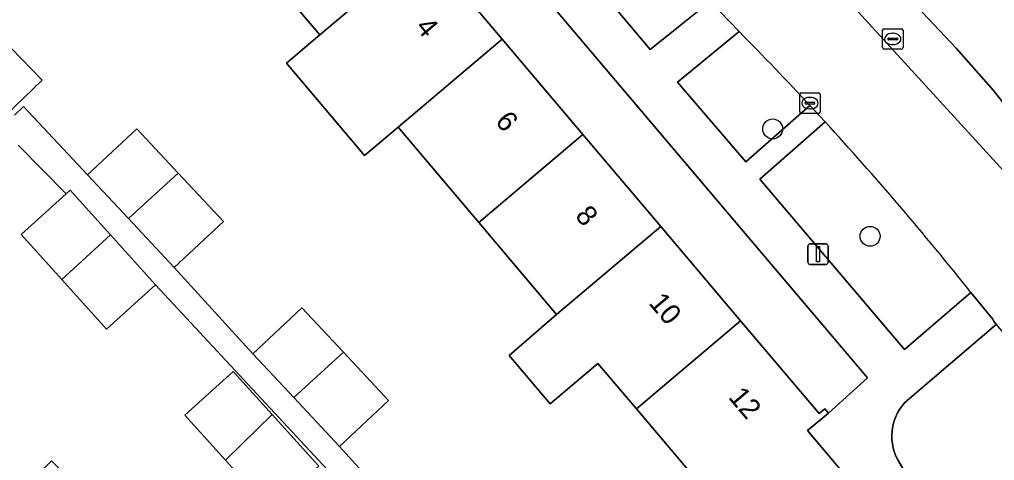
# Model space of a CAD drawing. Extents: x 157445 to 158888, y 383061 to 384688.
# Drawn here: x 158054.19 to 158101.94, y 383660.93 to 383682.54 of the extents above; entities that cross this region are included whole.
import ezdxf

# ---------------------------------------------------------------- set-up
doc = ezdxf.new("R2010")
doc.units = 0
for name, color, linetype in [('IMGEO_Boom', 7, 'Continuous'), ('IMGEO_Erf', 7, 'Continuous'), ('IMGEO_Groenvoorziening', 7, 'Continuous'), ('IMGEO_Kolk', 7, 'Continuous'), ('IMGEO_Lichtmast', 7, 'Continuous'), ('IMGEO_Pand', 7, 'Continuous'), ('IMGEO_Pand_nummerreeks', 7, 'Continuous'), ('IMGEO_Rijbaan_lokaal_open', 7, 'Continuous'), ('IMGEO_Voetpad_open', 7, 'Continuous')]:
    doc.layers.add(name, color=color, linetype=linetype)

msp = doc.modelspace()

# ---------------------------------------------------------------- linework, layer by layer
at = {"layer": 'IMGEO_Boom'}
for centre in [(158091.078, 383677.178), (158095.849, 383671.915)]:
    msp.add_circle(centre, 0.489, dxfattribs=at)
at = {"layer": 'IMGEO_Erf'}
for points in [[(158092.625, 383696.263), (158088.43, 383700.755), (158084.527, 383704.934), (158084.25, 383704.676), (158084.045, 383704.896), (158080.741, 383701.811), (158086.038, 383696.025), (158100.067, 383681.132), (158101.887, 383679.058), (158105.261, 383674.8), (158108.948, 383678.243), (158108.741, 383678.465), (158109.011, 383678.718), (158105.049, 383682.96), (158100.869, 383687.435), (158096.77, 383691.825)], [(158072.313, 383692.636), (158070.36, 383690.983), (158070.525, 383690.787), (158070.237, 383690.543), (158074, 383686.097), (158077.829, 383681.572), (158081.783, 383676.9), (158085.593, 383672.397), (158089.505, 383667.775), (158093.355, 383663.225), (158093.632, 383663.46), (158093.805, 383663.256), (158095.722, 383664.977)], [(158053.274, 383681.653), (158055.291, 383679.571), (158053.065, 383677.434), (158051.058, 383679.524), (158049.018, 383681.648), (158051.217, 383683.777)], [(158064.27, 383660.943), (158062.282, 383663.145), (158064.658, 383665.289), (158066.561, 383663.181), (158068.84, 383660.658), (158066.464, 383658.513)]]:
    msp.add_lwpolyline(points, close=True, dxfattribs=at)
for points in [[(158080.49, 383668.082), (158076.68, 383672.585), (158072.726, 383677.258), (158071.078, 383675.88), (158067.259, 383680.398), (158068.897, 383681.783), (158065.131, 383686.233)], [(158053.948, 383677.856), (158054.386, 383678.28), (158057.524, 383674.927), (158059.934, 383677.184), (158061.964, 383675.014), (158064.179, 383672.648), (158061.769, 383670.392), (158065.611, 383666.151), (158068.021, 383668.408), (158070.052, 383666.237), (158072.266, 383663.872), (158069.856, 383661.616), (158073.799, 383657.268)], [(158053.719, 383658.92), (158055.759, 383660.913), (158059.947, 383656.682), (158064.119, 383652.466), (158068.424, 383648.116), (158071.384, 383645.125), (158069.358, 383643.12), (158070.575, 383641.89), (158070.767, 383642.08), (158070.948, 383641.898), (158070.497, 383641.451), (158072.722, 383639.101), (158081.32, 383647.24), (158077.126, 383651.884), (158074.719, 383649.71), (158072.534, 383652.13), (158070.537, 383654.342), (158072.945, 383656.515), (158060.851, 383669.543), (158058.444, 383667.369), (158056.257, 383669.792), (158054.262, 383672.001), (158056.476, 383673.999), (158054.116, 383676.385)], [(158088.243, 383658.921), (158084.402, 383663.46), (158082.519, 383665.684), (158080.171, 383663.699), (158078.163, 383666.074), (158080.49, 383668.082)]]:
    msp.add_lwpolyline(points, dxfattribs=at)
at = {"layer": 'IMGEO_Groenvoorziening'}
msp.add_lwpolyline([(158081.806, 383690.454), (158079.964, 383692.414), (158078.718, 383693.741), (158078.291, 383694.107), (158077.833, 383694.433), (158077.347, 383694.717), (158076.838, 383694.957), (158076.31, 383695.15), (158075.767, 383695.295), (158075.212, 383695.391), (158074.806, 383695.43), (158074.307, 383695.428), (158073.811, 383695.381), (158073.321, 383695.29), (158073.153, 383695.248), (158085.078, 383681.064), (158088.008, 383683.429)], close=True, dxfattribs=at)
for points in [[(158089.434, 383681.946), (158086.414, 383679.474), (158089.769, 383675.56), (158092.902, 383678.334)], [(158093.643, 383677.531), (158090.443, 383674.723), (158097.528, 383666.368), (158100.789, 383669.164)], [(158102.019, 383667.598), (158097.557, 383663.779), (158097.416, 383663.61), (158097.291, 383663.43), (158097.182, 383663.238), (158097.091, 383663.038), (158097.018, 383662.831), (158096.964, 383662.618), (158096.929, 383662.401), (158096.914, 383662.181), (158096.918, 383661.961), (158096.942, 383661.743), (158096.985, 383661.527), (158097.048, 383661.316), (158097.129, 383661.112), (158097.203, 383660.961), (158101.786, 383653.06), (158105.141, 383646.908)]]:
    msp.add_lwpolyline(points, dxfattribs=at)
for centre, radius, start, end in [((157977.199, 383570.714), 158.017, 42.92697, 44.74268), ((157977.673, 383571.249), 157.305, 38.49534, 42.50392)]:
    msp.add_arc(centre, radius, start, end, dxfattribs=at)
at = {"layer": 'IMGEO_Kolk'}
for p, q in [((158096.46, 383681.163), (158096.46, 383682.015)), ((158096.535, 383682.089), (158097.387, 383682.089)), ((158096.948, 383681.869), (158096.973, 383681.869)), ((158097.461, 383682.015), (158097.461, 383681.163)), ((158096.719, 383681.583), (158096.719, 383681.595)), ((158097.157, 383681.546), (158096.759, 383681.546)), ((158096.762, 383681.632), (158097.16, 383681.632)), ((158096.971, 383681.309), (158096.946, 383681.309)), ((158097.203, 383681.595), (158097.203, 383681.583)), ((158097.387, 383681.089), (158096.535, 383681.089)), ((158092.401, 383678.016), (158092.401, 383678.868)), ((158092.476, 383678.942), (158093.328, 383678.942)), ((158093.402, 383678.868), (158093.402, 383678.016)), ((158092.66, 383678.436), (158092.66, 383678.448)), ((158093.098, 383678.399), (158092.7, 383678.399)), ((158092.703, 383678.485), (158093.101, 383678.485)), ((158092.889, 383678.722), (158092.914, 383678.722)), ((158093.144, 383678.448), (158093.144, 383678.436)), ((158093.328, 383677.942), (158092.476, 383677.942)), ((158092.912, 383678.162), (158092.887, 383678.162))]:
    msp.add_line(p, q, dxfattribs=at)
for points in [[(158096.46, 383681.163), (158096.46, 383682.015)], [(158096.535, 383682.089), (158097.387, 383682.089)], [(158097.461, 383682.015), (158097.461, 383681.163)], [(158097.387, 383681.089), (158096.535, 383681.089)], [(158092.401, 383678.016), (158092.401, 383678.868)], [(158092.476, 383678.942), (158093.328, 383678.942)], [(158093.402, 383678.868), (158093.402, 383678.016)], [(158093.328, 383677.942), (158092.476, 383677.942)]]:
    msp.add_lwpolyline(points, dxfattribs=at)
for centre, radius, start, end in [((158096.537, 383682.013), 0.0765, 91.552, 178.448), ((158096.537, 383682.013), 0.0765, 91.552, 178.448), ((158097.385, 383682.013), 0.0765, 1.552, 88.448), ((158097.385, 383682.013), 0.0765, 1.552, 88.448), ((158096.759, 383681.592), 0.0403, 85.8775, 175.7526), ((158096.756, 383681.582), 0.0366, 178.938, 274.7102), ((158097.16, 383681.589), 0.043, 264.8664, 352.4533), ((158097.164, 383681.594), 0.0386, 1.7309, 96.639), ((158096.537, 383681.165), 0.0765, 181.552, 268.448), ((158096.537, 383681.165), 0.0765, 181.552, 268.448), ((158097.385, 383681.165), 0.0765, 271.552, 358.448), ((158097.385, 383681.165), 0.0765, 271.552, 358.448), ((158092.478, 383678.866), 0.0765, 91.552, 178.448), ((158092.478, 383678.866), 0.0765, 91.552, 178.448), ((158093.326, 383678.866), 0.0765, 1.552, 88.448), ((158093.326, 383678.866), 0.0765, 1.552, 88.448), ((158092.7, 383678.445), 0.0403, 85.8775, 175.7526), ((158092.697, 383678.435), 0.0366, 178.938, 274.7102), ((158093.101, 383678.442), 0.043, 264.8664, 352.4533), ((158093.105, 383678.447), 0.0386, 1.7309, 96.639), ((158092.478, 383678.018), 0.0765, 181.552, 268.448), ((158092.478, 383678.018), 0.0765, 181.552, 268.448), ((158093.326, 383678.018), 0.0765, 271.552, 358.448), ((158093.326, 383678.018), 0.0765, 271.552, 358.448)]:
    msp.add_arc(centre, radius, start, end, dxfattribs=at)
for centre, major_axis, ratio, start_param, end_param in [((158096.947, 383681.589), (-0.387, 0.002), 0.722429, 4.712389, 7.853982), ((158096.972, 383681.589), (-0.39, 0.002), 0.717154, 1.570796, 4.712389), ((158092.888, 383678.442), (-0.387, 0.002), 0.722429, 4.712389, 7.853982), ((158092.913, 383678.442), (-0.39, 0.002), 0.717154, 1.570796, 4.712389)]:
    msp.add_ellipse(centre, major_axis=major_axis, ratio=ratio, start_param=start_param, end_param=end_param, dxfattribs=at)
at = {"layer": 'IMGEO_Lichtmast'}
for p, q in [((158092.803, 383670.641), (158092.803, 383671.441)), ((158092.803, 383671.441), (158092.803, 383670.641)), ((158092.903, 383671.541), (158093.693, 383671.541)), ((158093.693, 383671.541), (158092.903, 383671.541)), ((158093.793, 383671.441), (158093.793, 383670.641)), ((158093.793, 383670.641), (158093.793, 383671.441)), ((158093.693, 383670.541), (158092.903, 383670.541)), ((158092.903, 383670.541), (158093.693, 383670.541))]:
    msp.add_line(p, q, dxfattribs=at)
msp.add_lwpolyline([(158093.223, 383671.416), (158093.373, 383671.416), (158093.373, 383670.666), (158093.223, 383670.666), (158093.223, 383671.416)], dxfattribs=at)
for centre, start, end in [((158092.903, 383671.441), 90, 180), ((158092.903, 383671.441), 90, 180), ((158093.693, 383671.441), 0, 90), ((158093.693, 383671.441), 360, 90), ((158092.903, 383670.641), 180, 270), ((158092.903, 383670.641), 180, 270), ((158093.693, 383670.641), 270, 0), ((158093.693, 383670.641), 270, 0)]:
    msp.add_arc(centre, 0.1, start, end, dxfattribs=at)
at = {"layer": 'IMGEO_Pand'}
for points in [[(158074, 383686.097), (158070.237, 383690.543), (158070.525, 383690.787), (158070.36, 383690.983), (158066.544, 383687.753), (158064.686, 383686.181), (158064.846, 383685.992), (158065.131, 383686.233), (158068.897, 383681.783)], [(158072.726, 383677.258), (158077.829, 383681.572), (158074, 383686.097), (158068.897, 383681.783), (158067.259, 383680.398), (158071.078, 383675.88)], [(158053.274, 383681.653), (158051.058, 383679.524), (158053.065, 383677.434), (158055.291, 383679.571)], [(158076.68, 383672.585), (158081.783, 383676.9), (158077.829, 383681.572), (158072.726, 383677.258)], [(158061.964, 383675.014), (158059.934, 383677.184), (158057.524, 383674.927), (158059.528, 383672.786)], [(158085.593, 383672.397), (158081.783, 383676.9), (158076.68, 383672.585), (158080.49, 383668.082)], [(158061.964, 383675.014), (158059.528, 383672.786), (158061.769, 383670.392), (158064.179, 383672.648)], [(158056.67, 383674.174), (158056.476, 383673.999), (158054.262, 383672.001), (158056.257, 383669.792), (158058.65, 383671.981)], [(158085.593, 383672.397), (158080.49, 383668.082), (158078.163, 383666.074), (158080.171, 383663.699), (158082.519, 383665.684), (158084.402, 383663.46), (158089.505, 383667.775)], [(158058.65, 383671.981), (158056.257, 383669.792), (158058.444, 383667.369), (158060.851, 383669.543)], [(158067.616, 383664.009), (158070.052, 383666.237), (158068.021, 383668.408), (158065.611, 383666.151)], [(158089.505, 383667.775), (158084.402, 383663.46), (158088.243, 383658.921), (158087.941, 383658.665), (158088.124, 383658.449), (158088.385, 383658.67), (158090.381, 383656.311), (158090.136, 383656.104), (158090.324, 383655.883), (158094.937, 383659.925), (158095.138, 383660.101), (158094.951, 383660.322), (158094.707, 383660.115), (158092.782, 383662.391), (158093.805, 383663.256), (158093.632, 383663.46), (158093.355, 383663.225)], [(158067.616, 383664.009), (158069.856, 383661.616), (158072.266, 383663.872), (158070.052, 383666.237)], [(158064.27, 383660.943), (158066.561, 383663.181), (158064.658, 383665.289), (158062.282, 383663.145)], [(158064.27, 383660.943), (158066.464, 383658.513), (158068.84, 383660.658), (158066.561, 383663.181)]]:
    msp.add_lwpolyline(points, close=True, dxfattribs=at)
at = {"layer": 'IMGEO_Rijbaan_lokaal_open'}
for points in [[(158103.101, 383674.336), (158085.347, 383693.787), (158081.806, 383690.454), (158088.008, 383683.429), (158089.434, 383681.946)], [(158092.902, 383678.334), (158093.643, 383677.531)], [(158100.789, 383669.164), (158101.837, 383667.872), (158101.917, 383667.751), (158102.019, 383667.598), (158103.018, 383666.401)]]:
    msp.add_lwpolyline(points, dxfattribs=at)
for centre, radius, start, end in [((157977.199, 383570.714), 158.017, 42.92697, 44.74268), ((157977.673, 383571.249), 157.305, 38.49534, 42.50392)]:
    msp.add_arc(centre, radius, start, end, dxfattribs=at)
at = {"layer": 'IMGEO_Voetpad_open'}
for points in [[(158105.261, 383674.8), (158101.887, 383679.058), (158100.067, 383681.132), (158086.038, 383696.025), (158080.741, 383701.811), (158079.451, 383703.221), (158079.329, 383703.032), (158079.224, 383702.834), (158079.138, 383702.627), (158079.07, 383702.412), (158079.022, 383702.193), (158078.993, 383701.97), (158078.985, 383701.746), (158078.996, 383701.522), (158079.028, 383701.299), (158079.079, 383701.081), (158079.15, 383700.868), (158079.239, 383700.662), (158079.347, 383700.464), (158083.532, 383695.764), (158085.347, 383693.787), (158103.101, 383674.336)], [(158090.443, 383674.723), (158093.643, 383677.531), (158092.902, 383678.334), (158089.769, 383675.56), (158086.414, 383679.474), (158089.434, 383681.946), (158088.008, 383683.429), (158085.078, 383681.064), (158073.153, 383695.248), (158072.408, 383694.958), (158071.692, 383694.602), (158071.006, 383694.181), (158072.313, 383692.636), (158095.722, 383664.977), (158093.805, 383663.256), (158092.782, 383662.391), (158094.707, 383660.115), (158094.951, 383660.322), (158095.138, 383660.101), (158094.937, 383659.925), (158095.792, 383658.433), (158105.581, 383641.442)], [(158082.503, 383646.116), (158083.579, 383647.114), (158095.792, 383658.433), (158094.937, 383659.925), (158090.324, 383655.883), (158081.958, 383648.552), (158078.044, 383652.733), (158075.804, 383655.126), (158073.799, 383657.268), (158069.856, 383661.616), (158067.616, 383664.009), (158065.611, 383666.151), (158061.769, 383670.392), (158059.528, 383672.786), (158057.524, 383674.927), (158054.386, 383678.28), (158053.948, 383677.856)], [(158054.116, 383676.385), (158056.476, 383673.999), (158056.67, 383674.174), (158058.65, 383671.981), (158060.851, 383669.543), (158072.945, 383656.515), (158074.924, 383654.322), (158077.126, 383651.884), (158081.32, 383647.24), (158072.722, 383639.101), (158068.115, 383634.74), (158065.939, 383632.879)], [(158105.141, 383646.908), (158101.786, 383653.06), (158097.203, 383660.961), (158097.129, 383661.112), (158097.048, 383661.316), (158096.985, 383661.527), (158096.942, 383661.743), (158096.918, 383661.961), (158096.914, 383662.181), (158096.929, 383662.401), (158096.964, 383662.618), (158097.018, 383662.831), (158097.091, 383663.038), (158097.182, 383663.238), (158097.291, 383663.43), (158097.416, 383663.61), (158097.557, 383663.779), (158102.019, 383667.598), (158101.917, 383667.751), (158101.837, 383667.872), (158100.789, 383669.164), (158097.528, 383666.368), (158090.443, 383674.723)]]:
    msp.add_lwpolyline(points, dxfattribs=at)

# ---------------------------------------------------------------- texts
at = {"layer": 'IMGEO_Pand_nummerreeks'}
for s, p in [('4', (158073.539, 383682.144)), ('6', (158077.446, 383677.523)), ('8', (158081.357, 383672.898)), ('10', (158084.966, 383668.629)), ('12', (158088.87, 383664.012))]:
    msp.add_text(s, height=1, rotation=310.2167, dxfattribs=at).set_placement(p)

doc.saveas('drawing.dxf')
